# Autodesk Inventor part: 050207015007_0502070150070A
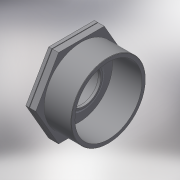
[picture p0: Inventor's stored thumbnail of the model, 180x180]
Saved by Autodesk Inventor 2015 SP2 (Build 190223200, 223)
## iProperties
Created: 2017-05
Part Number: 050207015007_0502070150070A
Material: Generic
Description: PLASSON REDUCING BUSHING 1.1/2"-3/4"
Document SubType Name: Modeling
Designer: KIM
Density: 1 g/cm^3
Appearance: Default
Author: KIM
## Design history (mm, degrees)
derived "050207.ipt"
feature "Solid1::050207.ipt"
tag "TaggingFeature1"
body "Solid1"
other parameters: "d1" = 47.803, "d5" = 21, "d8" = 0.37, "d12" = 0, "d15" = 37, "d19" = 0, "d30" = 9.25, "d31" = 4.625, "d33" = 24.117, "d34" = 43.0227, "d36" = 2.5, "d37" = 28.9404, "d38" = 24.42, "d39" = 21.7053, "d40" = 2.1, "d41" = 0, "H_" = 37, "R_" = 47.803, "l_2" = 21, "Rp_" = 24.117
